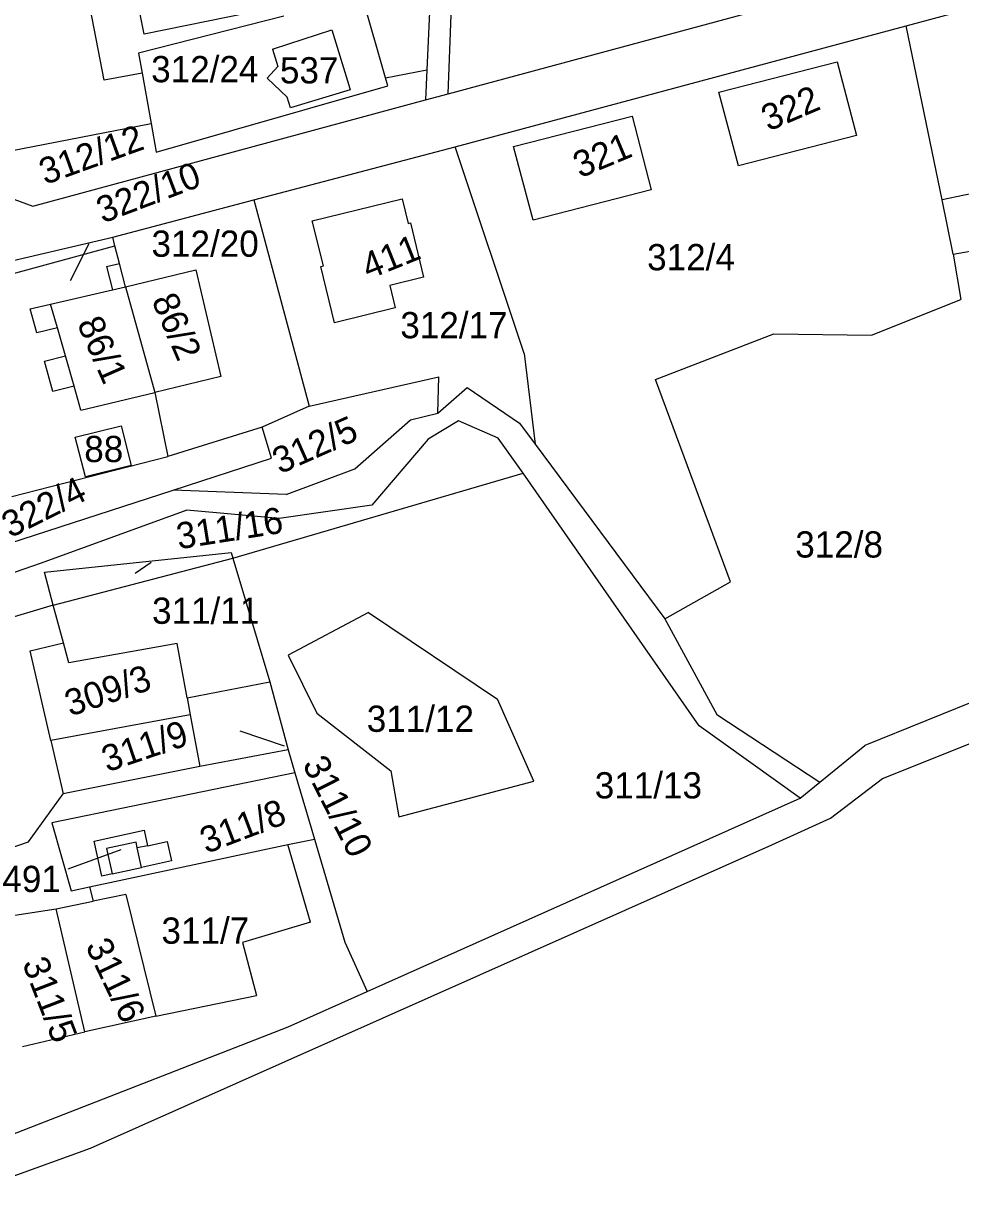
# Model space of a CAD drawing. Extents: x -805826 to -803822, y -1165880 to -1164382.
# Drawn here: x -805522.9 to -805401.4, y -1165129 to -1164975.4 of the extents above; entities that cross this region are included whole.
import ezdxf

# ---------------------------------------------------------------- set-up
doc = ezdxf.new("R2010")
doc.units = 0
for name, color, linetype in [('kn_celek - Cisla parcel pomocna', 7, 'Continuous'), ('kn_celek - Cisla pozemkovych parcel', 7, 'Continuous'), ('kn_celek - Cisla stavebnich parcel', 7, 'Continuous'), ('kn_celek - Hranice parcel', 7, 'Continuous'), ('kn_celek - Vnitrni kresby', 7, 'Continuous')]:
    doc.layers.add(name, color=color, linetype=linetype)

msp = doc.modelspace()

# ---------------------------------------------------------------- linework, layer by layer
at = {"layer": 'kn_celek - Cisla parcel pomocna'}
for p, q in [((-805516.83, -1165008.74), (-805514.41, -1165003.93)), ((-805508.46, -1165046.66), (-805506.36, -1165045.22)), ((-805494.86, -1165067.1), (-805489.14, -1165069.03)), ((-805510.28, -1165082.52), (-805517.17, -1165085))]:
    msp.add_line(p, q, dxfattribs=at)
at = {"layer": 'kn_celek - Hranice parcel'}
for p, q in [((-805468.91, -1164943.64), (-805470.61, -1164981.43)), ((-805467.86, -1164984.54), (-805466.91, -1164959.9)), ((-805512.48, -1164982.77), (-805516.26, -1164962.92)), ((-805467.86, -1164984.54), (-805410.52, -1164969.05)), ((-805475.98, -1164982.47), (-805479.02, -1164971.86)), ((-805408.45, -1164975.7), (-805398.47, -1164973.02)), ((-805489.17, -1164974.45), (-805508.02, -1164979.27)), ((-805466.93, -1164991.38), (-805408.45, -1164975.7)), ((-805403.8, -1164998.29), (-805408.45, -1164975.7)), ((-805488.51, -1164978.06), (-805482.92, -1164976.25)), ((-805482.92, -1164976.25), (-805480.75, -1164983.39)), ((-805490.65, -1164978.75), (-805488.51, -1164978.06)), ((-805490.65, -1164978.75), (-805489.95, -1164981)), ((-805508.02, -1164979.27), (-805507.55, -1164981.86)), ((-805432.77, -1164984.33), (-805417.4, -1164980.37)), ((-805417.4, -1164980.37), (-805414.93, -1164989.91)), ((-805507.55, -1164981.86), (-805512.48, -1164982.77)), ((-805507.55, -1164981.86), (-805506.38, -1164988.37)), ((-805489.95, -1164981), (-805491.32, -1164982.51)), ((-805475.98, -1164982.47), (-805470.61, -1164981.43)), ((-805470.61, -1164981.43), (-805470.78, -1164985.32)), ((-805505.71, -1164992.1), (-805475.69, -1164983.49)), ((-805491.32, -1164982.51), (-805488.75, -1164984.95)), ((-805480.75, -1164983.39), (-805480.55, -1164984.02)), ((-805475.69, -1164983.49), (-805475.98, -1164982.47)), ((-805488.31, -1164986.36), (-805488.75, -1164984.95)), ((-805480.55, -1164984.02), (-805488.31, -1164986.36)), ((-805470.78, -1164985.32), (-805467.86, -1164984.54)), ((-805430.21, -1164993.85), (-805432.77, -1164984.33)), ((-805521.7, -1164999.07), (-805470.78, -1164985.32)), ((-805459.38, -1164991.37), (-805444.01, -1164987.41)), ((-805444.01, -1164987.41), (-805441.55, -1164996.96)), ((-805526.2, -1164992.2), (-805506.38, -1164988.37)), ((-805506.38, -1164988.37), (-805505.71, -1164992.1)), ((-805414.93, -1164989.91), (-805430.21, -1164993.85)), ((-805493.07, -1164998.27), (-805466.93, -1164991.38)), ((-805458.02, -1165018.17), (-805466.93, -1164991.38)), ((-805456.82, -1165000.9), (-805459.38, -1164991.37)), ((-805527.44, -1164997.02), (-805521.7, -1164999.07)), ((-805441.55, -1164996.96), (-805456.82, -1165000.9)), ((-805511.35, -1165003.1), (-805493.07, -1164998.27)), ((-805493.07, -1164998.27), (-805485.86, -1165025.02)), ((-805485.47, -1165000.98), (-805473.81, -1164998.14)), ((-805473.81, -1164998.14), (-805473.03, -1165001.34)), ((-805402.36, -1165005.32), (-805403.8, -1164998.29)), ((-805484.04, -1165006.82), (-805485.47, -1165000.98)), ((-805473.03, -1165001.34), (-805472.74, -1165001.27)), ((-805472.74, -1165001.27), (-805471.04, -1165008.3)), ((-805530.57, -1165007.58), (-805511.35, -1165003.1)), ((-805511.07, -1165004.21), (-805511.35, -1165003.1)), ((-805526.47, -1165008.41), (-805511.07, -1165004.21)), ((-805510.48, -1165006.52), (-805511.07, -1165004.21)), ((-805402.36, -1165005.32), (-805398.43, -1165004.6)), ((-805512.14, -1165006.93), (-805510.48, -1165006.52)), ((-805509.71, -1165009.54), (-805510.48, -1165006.52)), ((-805402.36, -1165005.32), (-805401.37, -1165011.19)), ((-805512.14, -1165006.93), (-805511.36, -1165009.93)), ((-805509.71, -1165009.54), (-805500.57, -1165007.36)), ((-805500.57, -1165007.36), (-805497.35, -1165021.15)), ((-805484.36, -1165006.9), (-805484.04, -1165006.82)), ((-805482.58, -1165014.19), (-805484.36, -1165006.9)), ((-805509.71, -1165009.54), (-805505.91, -1165023.24)), ((-805471.04, -1165008.3), (-805475.44, -1165009.36)), ((-805475.44, -1165009.36), (-805474.72, -1165012.28)), ((-805518.87, -1165011.66), (-805511.36, -1165009.93)), ((-805412.96, -1165015.8), (-805401.37, -1165011.19)), ((-805522.07, -1165012.39), (-805519.4, -1165011.78)), ((-805521.21, -1165015.49), (-805522.07, -1165012.39)), ((-805519.4, -1165011.78), (-805518.87, -1165011.66)), ((-805474.72, -1165012.28), (-805482.58, -1165014.19)), ((-805518.52, -1165014.84), (-805521.21, -1165015.49)), ((-805517.48, -1165018.47), (-805518.52, -1165014.84)), ((-805440.96, -1165021.56), (-805425.63, -1165015.65)), ((-805425.63, -1165015.65), (-805412.96, -1165015.8)), ((-805520.2, -1165019.19), (-805517.48, -1165018.47)), ((-805458.02, -1165018.17), (-805456.57, -1165029.93)), ((-805519.1, -1165023.12), (-805520.2, -1165019.19)), ((-805497.35, -1165021.15), (-805505.91, -1165023.24)), ((-805485.86, -1165025.02), (-805469.08, -1165021.21)), ((-805469.2, -1165025.9), (-805469.08, -1165021.21)), ((-805431.26, -1165047.78), (-805440.96, -1165021.56)), ((-805516.36, -1165022.4), (-805519.1, -1165023.12)), ((-805515.47, -1165025.53), (-805516.36, -1165022.4)), ((-805515.47, -1165025.53), (-805505.91, -1165023.24)), ((-805505.91, -1165023.24), (-805504.2, -1165031.53)), ((-805469.2, -1165025.9), (-805465.41, -1165022.61)), ((-805465.41, -1165022.61), (-805458.6, -1165027.2)), ((-805485.86, -1165025.02), (-805491.96, -1165027.73)), ((-805472.74, -1165026.79), (-805469.2, -1165025.9)), ((-805516.22, -1165029.04), (-805510.27, -1165027.56)), ((-805510.27, -1165027.56), (-805508.95, -1165032.7)), ((-805491.96, -1165027.73), (-805504.2, -1165031.53)), ((-805490.75, -1165031.74), (-805491.96, -1165027.73)), ((-805479.96, -1165033.14), (-805472.74, -1165026.79)), ((-805466.53, -1165026.89), (-805470.43, -1165029.28)), ((-805461.38, -1165029.15), (-805466.53, -1165026.89)), ((-805458.6, -1165027.2), (-805456.57, -1165029.93)), ((-805514.89, -1165034.18), (-805516.22, -1165029.04)), ((-805470.43, -1165029.28), (-805477.75, -1165037.82)), ((-805458.13, -1165033.69), (-805461.38, -1165029.15)), ((-805456.57, -1165029.93), (-805439.76, -1165052.56)), ((-805524.44, -1165036.73), (-805504.2, -1165031.53)), ((-805503.53, -1165035.89), (-805490.75, -1165031.74)), ((-805508.95, -1165032.7), (-805514.89, -1165034.18)), ((-805495.78, -1165044.71), (-805458.13, -1165033.69)), ((-805488.87, -1165036.46), (-805479.96, -1165033.14)), ((-805435.33, -1165066.42), (-805458.13, -1165033.69)), ((-805535.71, -1165046.34), (-805503.53, -1165035.89)), ((-805488.87, -1165036.46), (-805503.53, -1165035.89)), ((-805501.74, -1165038.49), (-805520.63, -1165045.37)), ((-805489.76, -1165039.58), (-805501.74, -1165038.49)), ((-805477.75, -1165037.82), (-805489.76, -1165039.58)), ((-805520.21, -1165046.54), (-805495.99, -1165043.99)), ((-805519.07, -1165050.81), (-805495.78, -1165044.71)), ((-805495.99, -1165043.99), (-805495.78, -1165044.71)), ((-805495.78, -1165044.71), (-805490.96, -1165060.74)), ((-805520.63, -1165045.37), (-805534.93, -1165050.28)), ((-805519.07, -1165050.81), (-805520.21, -1165046.54)), ((-805439.76, -1165052.56), (-805431.26, -1165047.78)), ((-805519.07, -1165050.81), (-805528.36, -1165053.56)), ((-805517.75, -1165055.69), (-805519.07, -1165050.81)), ((-805478.19, -1165051.77), (-805488.58, -1165057.26)), ((-805478.19, -1165051.77), (-805461.44, -1165062.97)), ((-805439.76, -1165052.56), (-805433.03, -1165064.97)), ((-805522.04, -1165056.74), (-805517.75, -1165055.69)), ((-805517.05, -1165058.26), (-805517.75, -1165055.69)), ((-805519.37, -1165068.32), (-805522.04, -1165056.74)), ((-805503, -1165055.76), (-805517.05, -1165058.26)), ((-805501.71, -1165062.83), (-805503, -1165055.76)), ((-805488.58, -1165057.26), (-805484.87, -1165064.79)), ((-805501.71, -1165062.83), (-805490.96, -1165060.74)), ((-805490.96, -1165060.74), (-805488.62, -1165069.55)), ((-805394.66, -1165061.25), (-805413.81, -1165068.97)), ((-805501.71, -1165062.83), (-805501.3, -1165065.01)), ((-805456.74, -1165073.6), (-805461.44, -1165062.97)), ((-805411.54, -1165073.26), (-805384.61, -1165062.47)), ((-805484.87, -1165064.79), (-805475.3, -1165072.28)), ((-805501.3, -1165065.01), (-805519.37, -1165068.32)), ((-805501.3, -1165065.01), (-805500.05, -1165071.71)), ((-805422.2, -1165075.83), (-805435.33, -1165066.42)), ((-805433.03, -1165064.97), (-805419.65, -1165073.74)), ((-805519.37, -1165068.32), (-805517.78, -1165075.25)), ((-805419.65, -1165073.74), (-805413.81, -1165068.97)), ((-805488.62, -1165069.55), (-805500.05, -1165071.71)), ((-805488.62, -1165069.55), (-805487.73, -1165072.53)), ((-805487.73, -1165072.53), (-805519.24, -1165078.99)), ((-805500.05, -1165071.71), (-805517.78, -1165075.25)), ((-805487.73, -1165072.53), (-805485.2, -1165081.11)), ((-805475.3, -1165072.28), (-805474.26, -1165078.24)), ((-805474.26, -1165078.24), (-805456.74, -1165073.6)), ((-805422.2, -1165075.83), (-805419.65, -1165073.74)), ((-805418.3, -1165078.42), (-805411.54, -1165073.26)), ((-805522.25, -1165081.49), (-805517.78, -1165075.25)), ((-805478.36, -1165100.85), (-805422.2, -1165075.83)), ((-805425.87, -1165081.88), (-805418.3, -1165078.42)), ((-805519.24, -1165078.99), (-805516.74, -1165087.82)), ((-805513.74, -1165081.38), (-805507.29, -1165079.97)), ((-805507.29, -1165079.97), (-805506.84, -1165081.98)), ((-805550.96, -1165091.05), (-805522.25, -1165081.49)), ((-805512.76, -1165085.92), (-805513.74, -1165081.38)), ((-805506.84, -1165081.98), (-805504.27, -1165081.41)), ((-805504.27, -1165081.41), (-805503.72, -1165083.95)), ((-805488.64, -1165081.84), (-805485.2, -1165081.11)), ((-805485.2, -1165081.11), (-805481.24, -1165094.47)), ((-805514.37, -1165087.31), (-805488.64, -1165081.84)), ((-805514.21, -1165121.19), (-805425.87, -1165081.88)), ((-805485.72, -1165091.87), (-805488.64, -1165081.84)), ((-805511.42, -1165085.63), (-805507.61, -1165084.81)), ((-805503.72, -1165083.95), (-805507.61, -1165084.81)), ((-805511.42, -1165085.63), (-805512.76, -1165085.92)), ((-805516.74, -1165087.82), (-805514.37, -1165087.31)), ((-805514.37, -1165087.31), (-805513.87, -1165089.18)), ((-805518.7, -1165090.14), (-805513.87, -1165089.18)), ((-805509.66, -1165088.3), (-805513.87, -1165089.18)), ((-805509.66, -1165088.3), (-805505.76, -1165104.05)), ((-805527.3, -1165091.46), (-805518.7, -1165090.14)), ((-805514.95, -1165106.11), (-805518.7, -1165090.14)), ((-805485.72, -1165091.87), (-805494.54, -1165094.54)), ((-805494.54, -1165094.54), (-805492.69, -1165101.37)), ((-805481.24, -1165094.47), (-805478.36, -1165100.85)), ((-805505.76, -1165104.05), (-805492.69, -1165101.37)), ((-805488.62, -1165105.47), (-805478.36, -1165100.85)), ((-805505.76, -1165104.05), (-805514.95, -1165106.11)), ((-805532.9, -1165122.69), (-805488.62, -1165105.47)), ((-805523.03, -1165108.02), (-805514.95, -1165106.11)), ((-805535.76, -1165128.97), (-805514.21, -1165121.19))]:
    msp.add_line(p, q, dxfattribs=at)
at = {"layer": 'kn_celek - Vnitrni kresby'}
for p, q in [((-805507.27, -1164976.8), (-805508.87, -1164968.94)), ((-805493.65, -1164974.03), (-805507.27, -1164976.8)), ((-805387.94, -1164994.94), (-805403.8, -1164998.29)), ((-805511.36, -1165009.93), (-805509.71, -1165009.54)), ((-805518.52, -1165014.84), (-805519.4, -1165011.78)), ((-805516.36, -1165022.4), (-805517.48, -1165018.47)), ((-805508.33, -1165081.5), (-805512.14, -1165082.34)), ((-805508.16, -1165082.26), (-805508.33, -1165081.5)), ((-805512.14, -1165082.34), (-805511.42, -1165085.63)), ((-805506.84, -1165081.98), (-805508.16, -1165082.26)), ((-805507.61, -1165084.81), (-805508.16, -1165082.26))]:
    msp.add_line(p, q, dxfattribs=at)

# ---------------------------------------------------------------- texts
at = {"layer": 'kn_celek - Cisla parcel pomocna'}
for s, rotation, p in [('322/10', 20.799, (-805512.64, -1165001.35)), ('311/16', 8.991, (-805502.81, -1165043.57)), ('311/10', 296.91, (-805486.81, -1165071.4))]:
    msp.add_text(s, height=3.4, rotation=rotation, dxfattribs=at).set_placement(p)
msp.add_text('491', height=3.4, dxfattribs=at).set_placement((-805525.66, -1165087.98))
at = {"layer": 'kn_celek - Cisla pozemkovych parcel'}
for s, height, p in [('312/24', 3.4, (-805506.36, -1164983.03)), ('312/20', 3.4, (-805506.32, -1165005.65)), ('312/4', 3.4, (-805442.06, -1165007.4)), ('322/10', 0.005, (-805516.83, -1165008.74)), ('312/17', 3.4, (-805474.06, -1165016.21)), ('312/8', 3.4, (-805422.85, -1165044.63)), ('311/16', 0.005, (-805508.46, -1165046.66)), ('311/11', 3.4, (-805506.25, -1165053.22)), ('311/12', 3.4, (-805478.41, -1165067.22)), ('311/10', 0.005, (-805494.86, -1165067.1)), ('311/13', 3.4, (-805448.85, -1165075.85)), ('311/7', 3.4, (-805505.03, -1165094.68))]:
    msp.add_text(s, height=height, dxfattribs=at).set_placement(p)
for s, rotation, p in [('312/12', 19.881, (-805520.12, -1164996.36)), ('312/5', 23.895, (-805489.67, -1165033.86)), ('322/4', 26.703, (-805524.63, -1165042.16)), ('309/3', 18.45, (-805516.87, -1165065.25)), ('311/9', 18.621, (-805512.07, -1165072.48)), ('311/8', 20.853, (-805499.22, -1165083.05)), ('311/6', 295.533, (-805514.94, -1165094.96)), ('311/5', 291.177, (-805523.12, -1165097.19))]:
    msp.add_text(s, height=3.4, rotation=rotation, dxfattribs=at).set_placement(p)
at = {"layer": 'kn_celek - Cisla stavebnich parcel'}
for s, height, p in [('537', 3.4, (-805489.67, -1164983.18)), ('88', 3.4, (-805515.04, -1165032.26)), ('491', 0.005, (-805510.28, -1165082.52))]:
    msp.add_text(s, height=height, dxfattribs=at).set_placement(p)
for s, rotation, p in [('322', 23.094, (-805426.33, -1164989.43)), ('321', 22.635, (-805450.75, -1164995.5)), ('411', 21.834, (-805478.2, -1165008.63)), ('86/2', 293.355, (-805506.36, -1165011.27)), ('86/1', 293.751, (-805516.03, -1165014.29))]:
    msp.add_text(s, height=3.4, rotation=rotation, dxfattribs=at).set_placement(p)

doc.saveas('drawing.dxf')
